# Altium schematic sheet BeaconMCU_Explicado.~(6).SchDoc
size A4
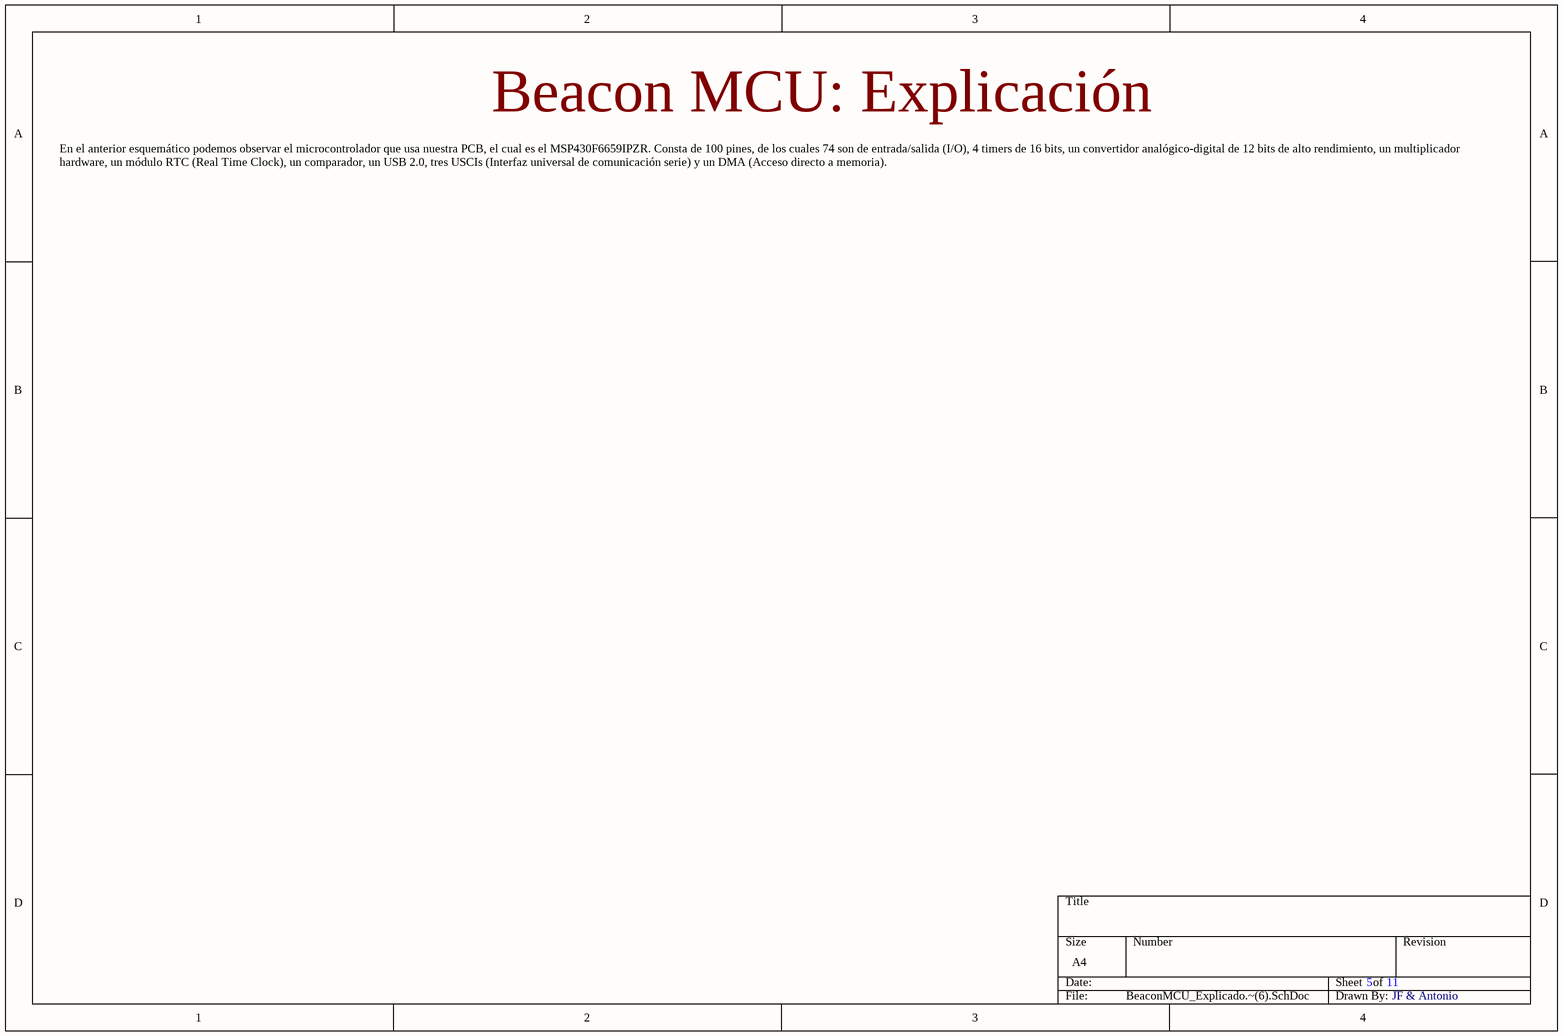
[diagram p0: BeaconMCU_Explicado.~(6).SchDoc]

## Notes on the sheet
- Beacon MCU: Explicación
- En el anterior esquemático podemos observar el microcontrolador que usa nuestra PCB, el cual es el MSP430F6659IPZR. Consta de 100 pines, de los cuales 74 son de entrada/salida (I/O), 4 timers de 16 bits, un convertidor analógico-digital de 12 bits de alto rendimiento, un multiplicador hardware, un módulo RTC (Real Time Clock), un comparador, un USB 2.0, tres USCIs (Interfaz universal de comunicación serie) y un DMA (Acceso directo a memoria).
- 5
- 11
- JF & Antonio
